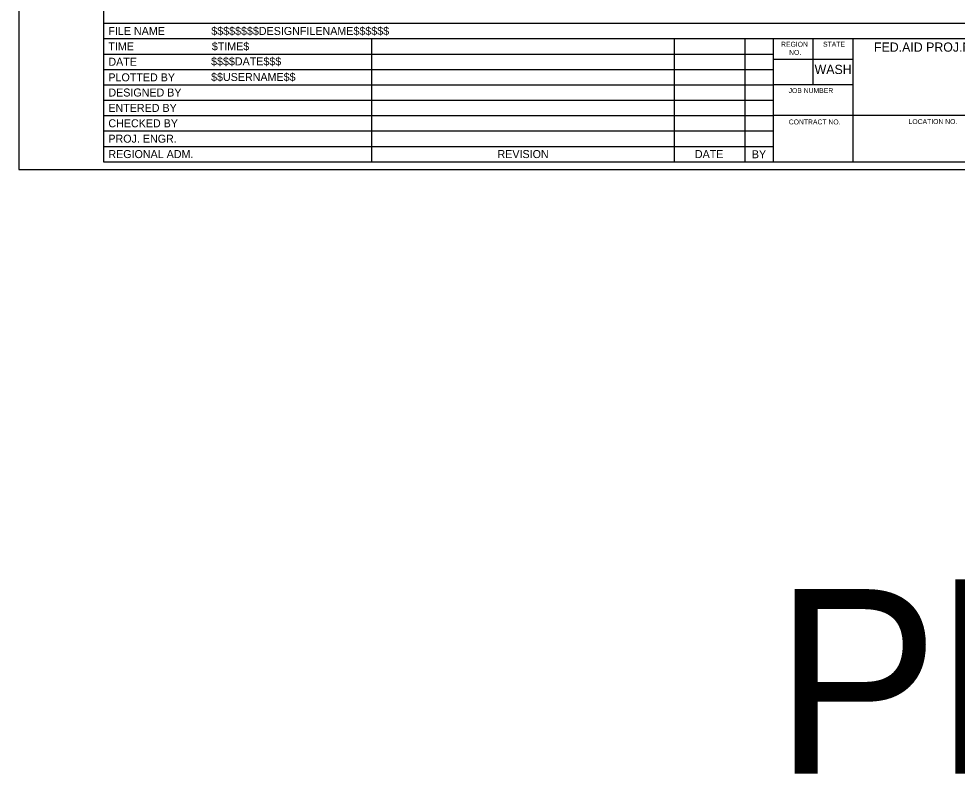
# Model space of a CAD drawing. Extents: x 99988 to 100172, y 99995 to 100047.
# Drawn here: x 99999.31 to 100006.94, y 99995.01 to 100001.16 of the extents above; entities that cross this region are included whole.
import ezdxf

# ---------------------------------------------------------------- set-up
doc = ezdxf.new("R2010")
doc.units = 0
for name, color, linetype in [('SH_GI_PlotLimits', 7, 'Continuous'), ('SH_GI_SheetBorder', 7, 'Continuous'), ('SH_GI_SheetLocationText', 7, 'Continuous'), ('SH_GI_SheetTextInCells', 7, 'Continuous'), ('SH_GI_TitleBlockText', 7, 'Continuous')]:
    doc.layers.add(name, color=color, linetype=linetype)

msp = doc.modelspace()

# ---------------------------------------------------------------- linework, layer by layer
at = {"layer": 'SH_GI_PlotLimits'}
msp.add_lwpolyline([(99999.3125, 99999.9375), (100015.8125, 99999.9375), (100015.8125, 100010.4375), (99999.3125, 100010.4375)], close=True, dxfattribs=at)
at = {"layer": 'SH_GI_SheetBorder'}
for p, q in [((100000, 100010.375), (100000, 100000)), ((100000, 100001.1259), (100015.75, 100001.1259)), ((100000, 100001.0008), (100007.4566, 100001.0008)), ((100002.179, 100001.0008), (100002.179, 100000)), ((100004.641, 100001.0008), (100004.641, 100000)), ((100005.2164, 100001.0008), (100005.2164, 100000)), ((100005.4451, 100001.0008), (100005.4451, 100000)), ((100005.7719, 100000.6255), (100005.7719, 100001.0008)), ((100006.0956, 100000), (100006.0956, 100001.0008)), ((100000, 100000.8757), (100002.1821, 100000.8757)), ((100002.1821, 100000.8757), (100005.4466, 100000.8757)), ((100006.0958, 100000.831), (100005.4466, 100000.831)), ((100000, 100000.7506), (100002.1821, 100000.7506)), ((100002.1821, 100000.7506), (100005.4466, 100000.7506)), ((100000, 100000.6255), (100005.4466, 100000.6255)), ((100006.0958, 100000.6255), (100005.4466, 100000.6255)), ((100000, 100000.5004), (100005.4466, 100000.5004)), ((100000, 100000.3753), (100005.4466, 100000.3753)), ((100007.4566, 100000.3753), (100005.4466, 100000.3753)), ((100000, 100000.2502), (100005.4466, 100000.2502)), ((100000, 100000.1251), (100005.4466, 100000.1251)), ((100000, 100000), (100015.75, 100000))]:
    msp.add_line(p, q, dxfattribs=at)

# ---------------------------------------------------------------- texts
at = {"layer": 'SH_GI_SheetLocationText'}
msp.add_text('Plot 1', height=1.5, dxfattribs=at).set_placement((100005.4547, 99995.0267))
at = {"layer": 'SH_GI_SheetTextInCells'}
for s, height, p in [('FILE NAME', 0.06505, (100000.041, 100001.0308)), ('TIME', 0.06505, (100000.041, 100000.9057)), ('REGION', 0.04003, (100005.5099, 100000.9352)), ('STATE', 0.04003, (100005.8511, 100000.9357)), ('FED.AID PROJ.NO.', 0.07506, (100006.2652, 100000.8945)), ('NO.', 0.04003, (100005.5752, 100000.869)), ('DATE', 0.06505, (100000.041, 100000.7806)), ('WASH', 0.07506, (100005.7826, 100000.7131)), ('PLOTTED BY', 0.06505, (100000.041, 100000.6538)), ('DESIGNED BY', 0.065052, (100000.041, 100000.5304)), ('JOB NUMBER', 0.04003, (100005.5712, 100000.5587)), ('ENTERED BY', 0.06505, (100000.041, 100000.4053)), ('CHECKED BY', 0.06505, (100000.041, 100000.2802)), ('CONTRACT NO.', 0.040032, (100005.5725, 100000.3037)), ('LOCATION NO.', 0.040032, (100006.5465, 100000.3067)), ('PROJ. ENGR.', 0.065052, (100000.041, 100000.1551)), ('REGIONAL ADM.', 0.065052, (100000.041, 100000.03)), ('REVISION', 0.06505, (100003.2048, 100000.03)), ('DATE', 0.06505, (100004.8091, 100000.03)), ('BY', 0.06505, (100005.2725, 100000.0285))]:
    msp.add_text(s, height=height, dxfattribs=at).set_placement(p)
at = {"layer": 'SH_GI_TitleBlockText'}
for s, height, p in [('$$$$$$$$DESIGNFILENAME$$$$$$', 0.065052, (100000.8775, 100001.0308)), ('$TIME$', 0.06505, (100000.882, 100000.9059)), ('$$$$DATE$$$', 0.065052, (100000.8759, 100000.7835)), ('$$USERNAME$$', 0.065052, (100000.8759, 100000.6567))]:
    msp.add_text(s, height=height, dxfattribs=at).set_placement(p)

doc.saveas('drawing.dxf')
